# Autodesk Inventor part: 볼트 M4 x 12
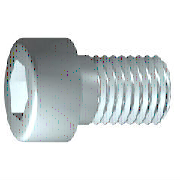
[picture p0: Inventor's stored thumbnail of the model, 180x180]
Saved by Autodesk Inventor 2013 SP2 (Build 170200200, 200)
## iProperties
IsCustomPart: 1
Created: 2012-02
Part Number: 볼트 M4 x 12
Material: 스테인리스강
Description: 6각 소켓 머리 캡 나사
Document SubType Name: Modeling
Standard: ISO 4762
Designer: mduedu
Standard Revision: Fourth edition 2004-03-01
Standards Organization: ISO
Language: ko-KR
Size Designation: M4 x 8
Categories: <MemberInstance><Categories><Category DisplayName="조임쇠" InternalName="e4da775c-781d-43d5-af7c-5136215cf5a6" Mnemonic="FSTN"><Category DisplayName="볼트" InternalN
Density: 7.75 g/cm^3
Author: mduedu
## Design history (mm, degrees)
sketch "스케치1"
  geometry: L1 (-1, 0)-(12, 0); L2 (12, 0)-(12, 2); L3 (12, 2)-(1.75, 2); L4 (1.75, 2)-(1.32, 2); L5 (1.32, 2)-(0, 2); L6 (0, 2)-(0, 3.5); L7 (0, 3.5)-(-4, 3.5); L8 (-4, 3.5)-(-4, 1.732); L9 (-4, 1.732)-(-2, 1.732); L10 (-2, 1.732)-(-1, 0); L11 (-7.2, 0)-(15.2, 0) reference; L12 (0, -0.7)-(0, 4.2) reference; L13 (1.75, 2)-(0, 2)
  constraints: 22 end point, 6 parallel, 2 collinear, 2 perpendicular, 1 horizontal, 1 point on line
  dimensions: "d1" = 10.25 distance from line of L3.end L2 (= GEL); "d2" = 0.42952 distance of L4.end L3.end (computed from GAL); "d3" = 4 distance between parallel lines of L8 L6 (= KOH); "d4" = 2 distance of L8.end L9.end (= INTI); "d5" = 60 deg angle of L10 L1; "d6" = 4 diameter of L3 L1 (= GD); "d7" = 4 diameter of L5 L1 (= BDM); "d8" = 3.4641 diameter of L9 L1 (= 1.1547 x SW); "d9" = 7 diameter of L7 L1 (= KOD); "d26" = 12 distance between parallel lines of L12 L2 (= NLG)
revolve "본체" sketch "스케치1" stored, may be unused: angle "d10" = 90 deg
sketch "스케치2"
  geometry: L1 (0, -4.9)-(0, 4.9) reference; L2 (-4.9, 0)-(4.9, 0) reference; L3 (1.732, 0)-(0.866, -1.5); L4 (0.866, -1.5)-(-0.866, -1.5); L5 (-0.866, -1.5)-(-1.732, 0); L6 (-1.732, 0)-(-0.866, 1.5); L7 (-0.866, 1.5)-(0.866, 1.5); L8 (0.866, 1.5)-(1.732, 0); 2 further points
  constraints: 12 end point, 1 coincident, 1 horizontal alignment, 1 point on line, 12 other
extrude "슬롯" join sketch "스케치2" stored distance "d11" = 10; taper "d12" = 0 deg
workplane "Work Plane1"
fillet "Fillet2" dims "d30" = 0.1 (= R)
body "Solid1"
fillet "모깎기1" dims "d17" = 0.4 (= RR)
feature "스레드" dims "d13" = 10.25 (= GEL), "d14" = 0
chamfer "모따기1" distance "d15" = 0.42941 (= -0.5 x SPD + 0.5 x GD); stored, may be unused: second distance "d16" = 0.42941 (= GUL), angle "d27" = 45 deg
other parameters: "GD" = 4 [user parameter; used in 2 equation terms], "NLG" = 12 [user parameter; used in 1 equation term], "GEL" = 10.25 [user parameter; used in 2 equation terms], "KOD" = 7 [user parameter; used in 1 equation term], "KOH" = 4 [user parameter; used in 1 equation term], "INTI" = 2 [user parameter; used in 1 equation term], "GAL" = 0.42941 (= 0.61345 x PTC) [user parameter; used in 1 equation term], "GUL" = 0.42941 (= 0.61345 x PTC) [user parameter; used in 1 equation term], "BDM" = 4 (= NND) [user parameter; used in 1 equation term], "SW" = 3 [user parameter; used in 2 equation terms], "RR" = 0.4 [user parameter; used in 1 equation term], "SPD" = 3.14117 (= NND - 1.2269 x PTC) [user parameter; used in 1 equation term], "d19" = 0, "d28" = 0, "d29" = 0, "R" = 0.1 [user parameter; used in 1 equation term], "TOA" = 30 deg [user parameter], "GD1" = 3.14117 (= THREADDIA - 1.2269 x PTC) [user parameter], "THREADDIA" = 4 [user parameter; used in 1 equation term], "FAWI" = 45 deg [user parameter], "TPU" = 14.28571 (computed from PTC) [user parameter], "PTC" = 0.7 [user parameter; used in 5 equation terms], "NND" = 4 [user parameter; used in 2 equation terms], "E0" = 3.465 (= 1.155 x SW) [user parameter]
